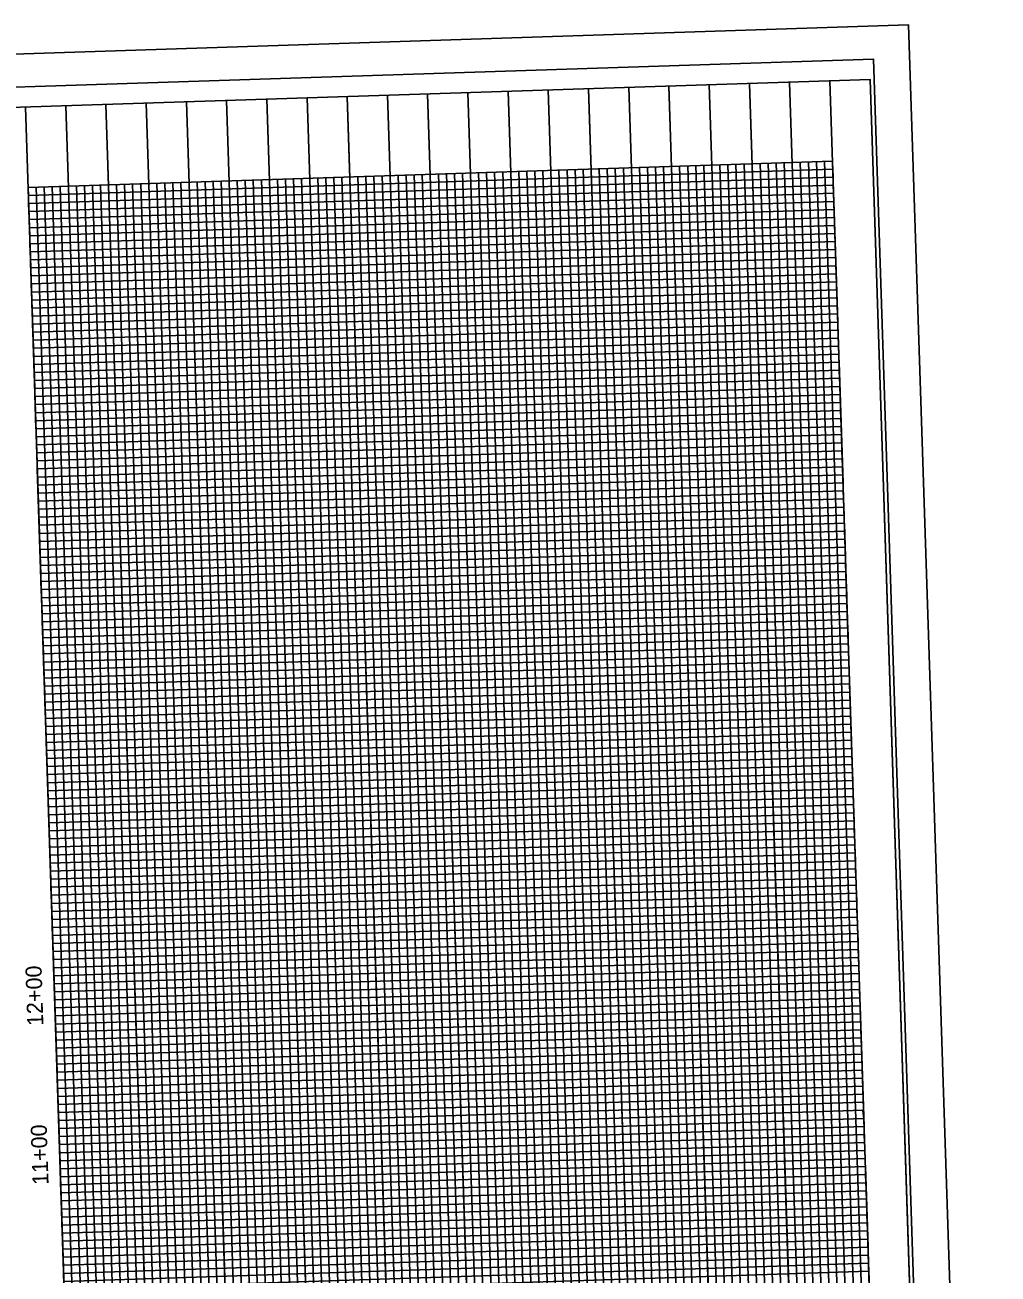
# Model space of a CAD drawing. Extents: x 1627314 to 1628469, y 762309 to 764245.
# Drawn here: x 1627865 to 1628469, y 763268 to 764044 of the extents above; entities that cross this region are included whole.
import ezdxf

# ---------------------------------------------------------------- set-up
doc = ezdxf.new("R2010")
doc.units = 0
for name, color, linetype in [('Exist Vertical Profile Horizontal Axis Label Major', 7, 'Continuous'), ('Sheet DOT Grid CELL', 7, 'Continuous'), ('Sheet Layout Profile Border Port 2', 7, 'Continuous'), ('Sheet Plot Border Inside CELL', 7, 'Continuous'), ('Sheet Plot Border Outside CELL', 7, 'Continuous'), ('Sheet Profile CELL', 7, 'Continuous'), ('Sheet Profile Grid Major CELL', 7, 'Continuous'), ('Sheet Profile Grid Middle CELL', 7, 'Continuous'), ('Sheet Profile Grid Minor CELL', 7, 'Continuous')]:
    doc.layers.add(name, color=color, linetype=linetype)

msp = doc.modelspace()

# ---------------------------------------------------------------- linework, layer by layer
at = {"layer": 'Sheet DOT Grid CELL'}
for p, q in [((1628213.88, 762504.01), (1628164.85, 764003.1)), ((1628263.85, 762505.65), (1628214.82, 764004.73)), ((1628313.83, 762507.28), (1628264.79, 764006.37)), ((1628363.8, 762508.92), (1628314.77, 764008)), ((1628013.99, 762497.47), (1627964.95, 763996.56)), ((1628063.96, 762499.11), (1628014.93, 763998.19)), ((1628113.93, 762500.74), (1628064.9, 763999.83)), ((1628163.91, 762502.38), (1628114.87, 764001.46)), ((1627914.04, 762494.2), (1627865.01, 763993.29)), ((1627964.01, 762495.84), (1627914.98, 763994.92)), ((1627866.64, 763943.43), (1628366.37, 763959.78)), ((1627868.27, 763893.46), (1628368, 763909.8)), ((1627869.91, 763843.48), (1628369.64, 763859.83)), ((1627871.54, 763793.51), (1628371.27, 763809.86)), ((1627873.18, 763743.54), (1628372.91, 763759.88)), ((1627874.81, 763693.56), (1628374.54, 763709.91)), ((1627876.44, 763643.59), (1628376.18, 763659.94)), ((1627878.08, 763593.62), (1628377.81, 763609.96)), ((1627879.71, 763543.64), (1628379.45, 763559.99)), ((1627881.35, 763493.67), (1628381.08, 763510.02)), ((1627882.98, 763443.7), (1628382.72, 763460.04)), ((1627884.62, 763393.72), (1628384.35, 763410.07)), ((1627886.25, 763343.75), (1628385.99, 763360.1)), ((1627887.89, 763293.78), (1628387.62, 763310.12))]:
    msp.add_line(p, q, dxfattribs=at)
at = {"layer": 'Sheet Layout Profile Border Port 2'}
msp.add_lwpolyline([(1627912.41, 762544.18), (1627866.64, 763943.43), (1628366.37, 763959.78), (1628412.14, 762560.52)], close=True, dxfattribs=at)
at = {"layer": 'Sheet Plot Border Inside CELL'}
msp.add_lwpolyline([(1628446.34, 762357.53), (1628391.86, 764023.14), (1627337.33, 763988.65), (1627391.81, 762323.04)], close=True, dxfattribs=at)
at = {"layer": 'Sheet Plot Border Outside CELL'}
msp.add_lwpolyline([(1628469.21, 762345.27), (1628413.63, 764044.37), (1627314.22, 764008.4), (1627369.79, 762309.31)], close=True, dxfattribs=at)
at = {"layer": 'Sheet Profile CELL'}
for p, q in [((1628364.74, 764009.75), (1628413.77, 762510.55)), ((1628438.76, 762511.37), (1628389.72, 764010.57)), ((1627914.04, 762494.2), (1627865, 763993.4))]:
    msp.add_line(p, q, dxfattribs=at)
msp.add_lwpolyline([(1627340.28, 763976.24), (1627389.32, 762477.04), (1628438.76, 762511.37), (1628389.72, 764010.57)], close=True, dxfattribs=at)
at = {"layer": 'Sheet Profile Grid Major CELL'}
for p, q in [((1627868.27, 763893.46), (1627866.64, 763943.43)), ((1628368, 763909.8), (1628368, 763909.8)), ((1627871.54, 763793.51), (1627869.91, 763843.48)), ((1627874.81, 763693.56), (1627873.18, 763743.54)), ((1627878.08, 763593.62), (1627876.44, 763643.59)), ((1627881.35, 763493.67), (1627879.71, 763543.64)), ((1627884.62, 763393.72), (1627882.98, 763443.7)), ((1627887.89, 763293.78), (1627886.25, 763343.75))]:
    msp.add_line(p, q, dxfattribs=at)
for points in [[(1628164.84, 764003.21), (1628213.88, 762504.01), (1628263.85, 762505.65), (1628214.82, 764004.85)], [(1628264.79, 764006.48), (1628313.83, 762507.28), (1628313.83, 762507.28), (1628363.8, 762508.92), (1628314.76, 764008.11)], [(1628364.74, 764009.75), (1628413.77, 762510.55)], [(1627964.95, 763996.67), (1628013.99, 762497.47), (1628063.96, 762499.11), (1628014.92, 763998.31)], [(1628064.9, 763999.94), (1628113.93, 762500.74), (1628163.91, 762502.38), (1628114.87, 764001.58)], [(1627914.98, 763995.04), (1627964.01, 762495.84)], [(1628389.25, 763260.15), (1628387.62, 763310.12), (1627887.89, 763293.78), (1627886.25, 763343.75), (1628385.99, 763360.1), (1628384.35, 763410.07), (1627884.62, 763393.72), (1627882.98, 763443.7), (1628382.72, 763460.04), (1628381.08, 763510.02), (1627881.35, 763493.67), (1627879.71, 763543.64), (1628379.45, 763559.99), (1628377.81, 763609.96), (1627878.08, 763593.62), (1627876.44, 763643.59), (1628376.18, 763659.94), (1628374.54, 763709.91), (1627874.81, 763693.56), (1627873.18, 763743.54), (1628372.91, 763759.88), (1628371.27, 763809.86), (1627871.54, 763793.51), (1627869.91, 763843.48), (1628369.64, 763859.83), (1628368, 763909.8), (1628368, 763909.8), (1627868.27, 763893.46), (1627866.64, 763943.43), (1628366.37, 763959.78)]]:
    msp.add_lwpolyline(points, dxfattribs=at)
at = {"layer": 'Sheet Profile Grid Middle CELL'}
for points in [[(1628139.86, 764002.39), (1628188.89, 762503.2), (1628238.87, 762504.83), (1628189.83, 764004.03)], [(1628239.8, 764005.66), (1628288.84, 762506.46), (1628338.81, 762508.1), (1628289.78, 764007.3)], [(1628339.75, 764008.93), (1628388.79, 762509.73)], [(1627939.96, 763995.85), (1627989, 762496.66), (1628038.97, 762498.29), (1627989.94, 763997.49)], [(1628039.91, 763999.12), (1628088.95, 762499.93), (1628138.92, 762501.56), (1628089.88, 764000.76)], [(1627939.03, 762495.02), (1627889.99, 763994.22)], [(1627890.34, 763218.82), (1627888.7, 763268.79), (1628388.44, 763285.14), (1628386.8, 763335.11), (1627887.07, 763318.76), (1627885.44, 763368.74), (1628385.17, 763385.08), (1628383.53, 763435.06), (1627883.8, 763418.71), (1627882.17, 763468.68), (1628381.9, 763485.03), (1628380.26, 763535), (1627880.53, 763518.66), (1627878.9, 763568.63), (1628378.63, 763584.98), (1628376.99, 763634.95), (1627877.26, 763618.6), (1627875.63, 763668.58), (1628375.36, 763684.92), (1628373.73, 763734.9), (1627873.99, 763718.55), (1627872.36, 763768.52), (1628372.09, 763784.87), (1628370.46, 763834.84), (1627870.72, 763818.5), (1627869.09, 763868.47), (1628368.82, 763884.82), (1628367.19, 763934.79), (1627867.45, 763918.44)]]:
    msp.add_lwpolyline(points, dxfattribs=at)
at = {"layer": 'Sheet Profile Grid Minor CELL'}
for p, q in [((1628317.19, 762557.42), (1628271.42, 763956.67)), ((1628276.42, 763956.83), (1628322.19, 762557.58)), ((1628327.18, 762557.75), (1628281.42, 763957)), ((1628286.41, 763957.16), (1628332.18, 762557.91)), ((1628342.18, 762558.24), (1628296.41, 763957.49)), ((1628301.4, 763957.65), (1628347.17, 762558.4)), ((1628352.17, 762558.56), (1628306.4, 763957.81)), ((1628311.4, 763957.98), (1628357.17, 762558.73)), ((1628367.16, 762559.05), (1628321.39, 763958.3)), ((1628326.39, 763958.47), (1628372.16, 762559.22)), ((1628377.16, 762559.38), (1628331.39, 763958.63)), ((1628336.39, 763958.8), (1628382.16, 762559.54)), ((1628392.15, 762559.87), (1628346.38, 763959.12)), ((1628351.38, 763959.29), (1628397.15, 762560.03)), ((1628402.14, 762560.2), (1628356.37, 763959.45)), ((1628361.37, 763959.61), (1628361.37, 763959.61)), ((1628407.14, 762560.36), (1628361.37, 763959.61)), ((1628077.32, 762549.57), (1628031.55, 763948.82)), ((1628036.55, 763948.99), (1628082.32, 762549.74)), ((1628092.31, 762550.06), (1628046.54, 763949.31)), ((1628051.54, 763949.48), (1628097.31, 762550.23)), ((1628102.3, 762550.39), (1628056.54, 763949.64)), ((1628061.53, 763949.8), (1628107.15, 762550.55)), ((1628117.3, 762550.88), (1628071.53, 763950.13)), ((1628076.52, 763950.3), (1628122.29, 762551.04)), ((1628127.29, 762551.21), (1628081.52, 763950.46)), ((1628086.52, 763950.62), (1628132.29, 762551.37)), ((1628142.28, 762551.7), (1628096.51, 763950.95)), ((1628101.51, 763951.11), (1628147.28, 762551.86)), ((1628152.28, 762552.02), (1628106.51, 763951.28)), ((1628111.51, 763951.44), (1628157.28, 762552.19)), ((1628167.27, 762552.51), (1628121.5, 763951.77)), ((1628126.5, 763951.93), (1628172.27, 762552.68)), ((1628177.26, 762552.84), (1628131.5, 763952.09)), ((1628136.49, 763952.26), (1628182.26, 762553)), ((1628192.26, 762553.33), (1628146.49, 763952.58)), ((1628151.48, 763952.75), (1628197.25, 762553.5)), ((1628202.25, 762553.66), (1628156.48, 763952.91)), ((1628161.48, 763953.07), (1628207.25, 762553.82)), ((1628217.24, 762554.15), (1628171.47, 763953.4)), ((1628176.47, 763953.56), (1628222.24, 762554.31)), ((1628227.24, 762554.48), (1628181.47, 763953.73)), ((1628186.47, 763953.89), (1628232.24, 762554.64)), ((1628242.23, 762554.97), (1628196.46, 763954.22)), ((1628201.46, 763954.38), (1628247.23, 762555.13)), ((1628252.22, 762555.29), (1628206.46, 763954.55)), ((1628211.45, 763954.71), (1628257.22, 762555.46)), ((1628267.22, 762555.78), (1628221.45, 763955.04)), ((1628226.44, 763955.2), (1628272.21, 762555.95)), ((1628277.21, 762556.11), (1628231.44, 763955.36)), ((1628236.44, 763955.53), (1628282.21, 762556.27)), ((1628292.2, 762556.6), (1628246.43, 763955.85)), ((1628251.43, 763956.02), (1628297.2, 762556.76)), ((1628302.2, 762556.93), (1628256.43, 763956.18)), ((1628261.43, 763956.34), (1628307.2, 762557.09)), ((1627917.4, 762544.34), (1627871.63, 763943.59)), ((1627876.63, 763943.76), (1627922.4, 762544.5)), ((1627927.4, 762544.67), (1627881.63, 763943.92)), ((1627886.63, 763944.08), (1627932.4, 762544.83)), ((1627942.39, 762545.16), (1627896.62, 763944.41)), ((1627901.62, 763944.57), (1627947.39, 762545.32)), ((1627952.38, 762545.49), (1627906.62, 763944.74)), ((1627911.61, 763944.9), (1627957.38, 762545.65)), ((1627967.38, 762545.98), (1627921.61, 763945.23)), ((1627926.6, 763945.39), (1627972.37, 762546.14)), ((1627977.37, 762546.3), (1627931.6, 763945.55)), ((1627936.6, 763945.72), (1627982.37, 762546.47)), ((1627992.36, 762546.79), (1627946.59, 763946.05)), ((1627951.59, 763946.21), (1627997.36, 762546.96)), ((1628002.36, 762547.12), (1627956.59, 763946.37)), ((1627961.59, 763946.54), (1628007.36, 762547.28)), ((1628017.35, 762547.61), (1627971.58, 763946.86)), ((1627976.58, 763947.03), (1628022.35, 762547.77)), ((1628027.34, 762547.94), (1627981.58, 763947.19)), ((1627986.57, 763947.35), (1628032.34, 762548.1)), ((1628042.34, 762548.43), (1627996.57, 763947.68)), ((1628001.56, 763947.84), (1628047.33, 762548.59)), ((1628052.33, 762548.75), (1628006.56, 763948.01)), ((1628011.56, 763948.17), (1628057.33, 762548.92)), ((1628067.32, 762549.25), (1628021.55, 763948.5)), ((1628026.55, 763948.66), (1628072.32, 762549.41))]:
    msp.add_line(p, q, dxfattribs=at)
for points in [[(1628374.87, 763699.91), (1628374.71, 763704.91), (1627874.97, 763688.57), (1627874.65, 763698.56), (1628374.38, 763714.91), (1628374.22, 763719.9), (1627874.48, 763703.56), (1627874.32, 763708.56), (1628374.05, 763724.9), (1628373.89, 763729.9), (1627874.16, 763713.55), (1627873.83, 763723.55), (1628373.56, 763739.89), (1628373.4, 763744.89), (1627873.67, 763728.54), (1627873.5, 763733.54), (1628373.24, 763749.89), (1628373.07, 763754.89), (1627873.34, 763738.54), (1627873.01, 763748.53), (1628372.74, 763764.88), (1628372.58, 763769.88), (1627872.85, 763753.53), (1627872.68, 763758.53), (1628372.42, 763774.87), (1628372.25, 763779.87), (1627872.52, 763763.53), (1627872.19, 763773.52), (1628371.93, 763789.87), (1628371.76, 763794.86), (1627872.03, 763778.52), (1627871.87, 763783.52), (1628371.6, 763799.86), (1628371.44, 763804.86), (1627871.7, 763788.51), (1627871.38, 763798.51), (1628371.11, 763814.85), (1628370.95, 763819.85), (1627871.21, 763803.5), (1627871.05, 763808.5), (1628370.78, 763824.85), (1628370.62, 763829.85), (1627870.89, 763813.5), (1627870.56, 763823.49), (1628370.29, 763839.84), (1628370.13, 763844.84), (1627870.4, 763828.49), (1627870.23, 763833.49), (1628369.97, 763849.83), (1628369.8, 763854.83), (1627870.07, 763838.49), (1627869.74, 763848.48), (1628369.48, 763864.83), (1628369.31, 763869.82), (1627869.58, 763853.48), (1627869.42, 763858.48), (1628369.15, 763874.82), (1628368.99, 763879.82), (1627869.25, 763863.47), (1627868.93, 763873.47), (1628368.66, 763889.81), (1628368.49, 763894.81), (1627868.76, 763878.46), (1627868.6, 763883.46), (1628368.33, 763899.81), (1628368.17, 763904.81), (1627868.43, 763888.46), (1627868.11, 763898.45), (1628367.84, 763914.8), (1628367.68, 763919.8), (1627867.94, 763903.45), (1627867.78, 763908.45), (1628367.51, 763924.79), (1628367.35, 763929.79), (1627867.62, 763913.45), (1627867.29, 763923.44), (1628367.02, 763939.79), (1628366.86, 763944.78), (1627867.13, 763928.44), (1627866.96, 763933.44), (1628366.7, 763949.78), (1628366.53, 763954.78), (1627866.8, 763938.43), (1627866.64, 763943.43)], [(1628384.84, 763395.08), (1627885.11, 763378.73), (1627884.94, 763383.73), (1628384.68, 763400.08), (1628384.51, 763405.07), (1627884.78, 763388.73), (1627884.45, 763398.72), (1628384.19, 763415.07), (1628384.02, 763420.06), (1627884.29, 763403.72), (1627884.13, 763408.72), (1628383.86, 763425.06), (1628383.7, 763430.06), (1627883.96, 763413.71), (1627883.64, 763423.71), (1628383.37, 763440.05), (1628383.21, 763445.05), (1627883.47, 763428.7), (1627883.31, 763433.7), (1628383.04, 763450.05), (1628382.88, 763455.05), (1627883.15, 763438.7), (1627882.82, 763448.69), (1628382.55, 763465.04), (1628382.39, 763470.04), (1627882.66, 763453.69), (1627882.49, 763458.69), (1628382.23, 763475.04), (1628382.06, 763480.03), (1627882.33, 763463.69), (1627882, 763473.68), (1628381.74, 763490.03), (1628381.57, 763495.02), (1627881.84, 763478.68), (1627881.68, 763483.68), (1628381.41, 763500.02), (1628381.24, 763505.02), (1627881.51, 763488.67), (1627881.19, 763498.67), (1628380.92, 763515.01), (1628380.75, 763520.01), (1627881.02, 763503.66), (1627880.86, 763508.66), (1628380.59, 763525.01), (1628380.43, 763530.01), (1627880.69, 763513.66), (1627880.37, 763523.65), (1628380.1, 763540), (1628379.94, 763545), (1627880.2, 763528.65), (1627880.04, 763533.65), (1628379.77, 763550), (1628379.61, 763554.99), (1627879.88, 763538.65), (1627879.55, 763548.64), (1628379.28, 763564.99), (1628379.12, 763569.98), (1627879.39, 763553.64), (1627879.22, 763558.64), (1628378.96, 763574.98), (1628378.79, 763579.98), (1627879.06, 763563.63), (1627878.73, 763573.63), (1628378.47, 763589.97), (1628378.3, 763594.97), (1627878.57, 763578.62), (1627878.41, 763583.62), (1628378.14, 763599.97), (1628377.98, 763604.97), (1627878.24, 763588.62), (1627877.92, 763598.61), (1628377.65, 763614.96), (1628377.49, 763619.96), (1627877.75, 763603.61), (1627877.59, 763608.61), (1628377.32, 763624.95), (1628377.16, 763629.95), (1627877.43, 763613.61), (1627877.1, 763623.6), (1628376.83, 763639.95), (1628376.67, 763644.94), (1627876.93, 763628.6), (1627876.77, 763633.6), (1628376.5, 763649.94), (1628376.34, 763654.94), (1627876.61, 763638.59), (1627876.28, 763648.59), (1628376.01, 763664.93), (1628375.85, 763669.93), (1627876.12, 763653.58), (1627875.95, 763658.58), (1628375.69, 763674.93), (1628375.52, 763679.93), (1627875.79, 763663.58), (1627875.46, 763673.57), (1628375.2, 763689.92), (1628375.03, 763694.92), (1627875.3, 763678.57), (1627875.14, 763683.57), (1628374.87, 763699.91)], [(1627889.03, 763258.8), (1628388.76, 763275.14), (1628388.6, 763280.14), (1627888.87, 763263.79), (1627888.54, 763273.79), (1628388.27, 763290.13), (1628388.11, 763295.13), (1627888.38, 763278.79), (1627888.21, 763283.78), (1628387.95, 763300.13), (1628387.78, 763305.13), (1627888.05, 763288.78), (1627887.72, 763298.77), (1628387.46, 763315.12), (1628387.29, 763320.12), (1627887.56, 763303.77), (1627887.4, 763308.77), (1628387.13, 763325.12), (1628386.97, 763330.11), (1627887.23, 763313.77), (1627886.91, 763323.76), (1628386.64, 763340.11), (1628386.48, 763345.1), (1627886.74, 763328.76), (1627886.58, 763333.76), (1628386.31, 763350.1), (1628386.15, 763355.1), (1627886.42, 763338.75), (1627886.09, 763348.75), (1628385.82, 763365.09), (1628385.12, 763369.77), (1628385.66, 763370.09), (1627885.93, 763353.75), (1627885.76, 763358.74), (1628385.49, 763375.09), (1628385.33, 763380.09), (1627885.6, 763363.74), (1627885.27, 763373.73), (1628385, 763390.08), (1628384.84, 763395.08)], [(1628389.09, 763265.15), (1628388.93, 763270.14), (1627889.19, 763253.8)]]:
    msp.add_lwpolyline(points, dxfattribs=at)

# ---------------------------------------------------------------- texts
at = {"layer": 'Exist Vertical Profile Horizontal Axis Label Major'}
for s, p in [('12+00', (1627876.17, 763422.63)), ('11+00', (1627879.4, 763323.91))]:
    msp.add_text(s, height=10, rotation=91.87347, dxfattribs=at).set_placement(p)

doc.saveas('drawing.dxf')
